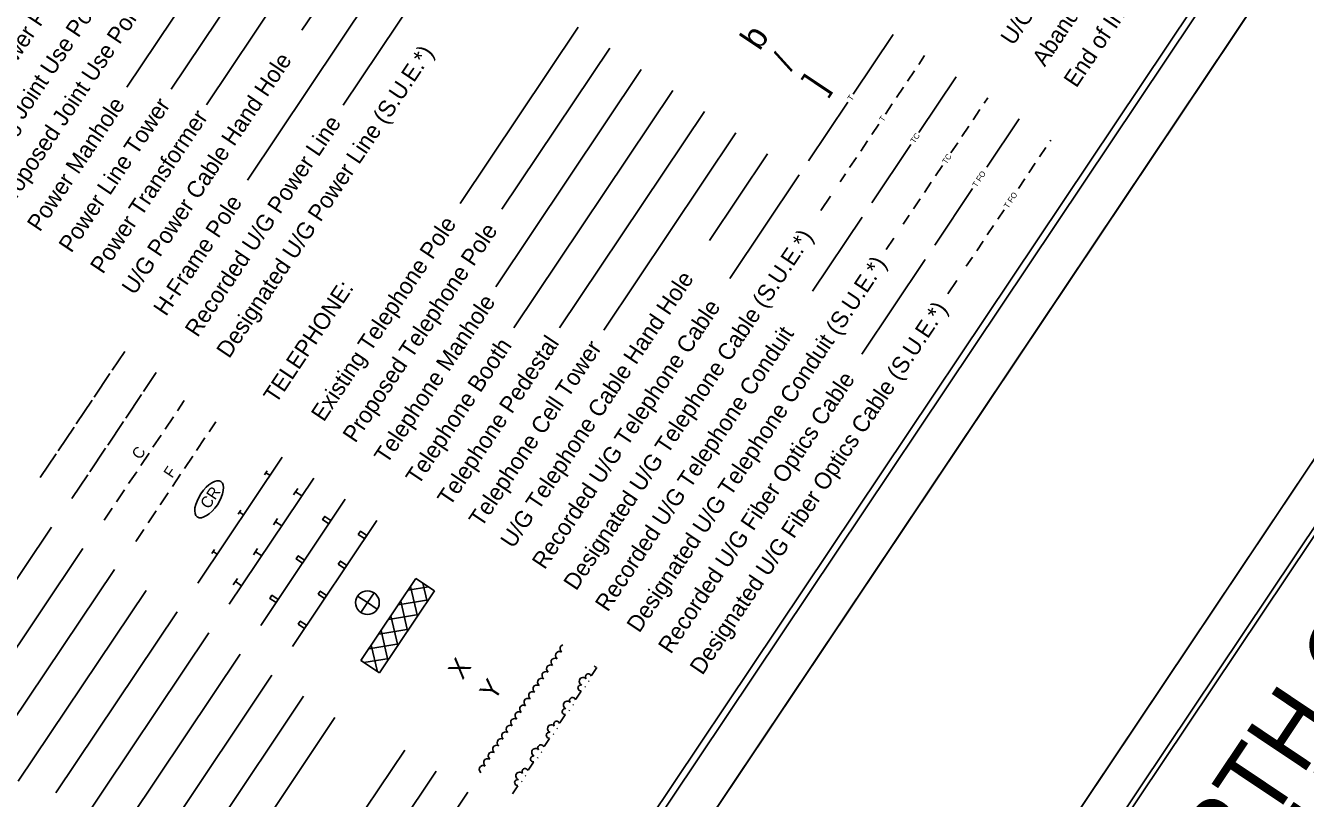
# Model space of a CAD drawing. Extents: x 1715610 to 1720914, y 798298 to 802505.
# Drawn here: x 1719036 to 1719710, y 799695 to 800102 of the extents above; entities that cross this region are included whole.
import ezdxf

# ---------------------------------------------------------------- set-up
doc = ezdxf.new("R2010")
doc.units = 0
for name, color, linetype in [('Prop WCC CELL', 7, 'Continuous'), ('Sheet Cutting Line CELL', 7, 'Continuous'), ('Sheet Plan CELL', 7, 'Continuous'), ('Sheet Plot Border Inside CELL', 7, 'Continuous'), ('Sheet Plot Border Outside CELL', 7, 'Continuous'), ('Sheet Symbology CELL', 7, 'Continuous'), ('Sheet Title CELL', 7, 'Continuous')]:
    doc.layers.add(name, color=color, linetype=linetype)

msp = doc.modelspace()

# ---------------------------------------------------------------- linework, layer by layer
at = {"layer": 'Prop WCC CELL'}
msp.add_ellipse((1719132.93, 799852.57), major_axis=(6.24, 9.32), ratio=0.462467, dxfattribs=at)
at = {"layer": 'Sheet Cutting Line CELL'}
for p, q in [((1718909.86, 798957.44), (1719846.53, 800356.9)), ((1720004.29, 800305.92), (1719067.89, 798906.88))]:
    msp.add_line(p, q, dxfattribs=at)
at = {"layer": 'Sheet Plan CELL'}
msp.add_lwpolyline([(1720013.54, 800279.28), (1719179.2, 799032.73), (1720051.79, 798448.69), (1720886.12, 799695.24)], close=True, dxfattribs=at)
at = {"layer": 'Sheet Plot Border Inside CELL'}
for points in [[(1718898.43, 798980.73), (1719825.37, 800365.65), (1718948.55, 800952.52), (1718021.61, 799567.6)], [(1719968.49, 798319.74), (1720895.15, 799704.24), (1720018.41, 800291.06), (1719091.75, 798906.55)]]:
    msp.add_lwpolyline(points, close=True, dxfattribs=at)
at = {"layer": 'Sheet Plot Border Outside CELL'}
for points in [[(1718909.86, 798957.44), (1719846.53, 800356.9), (1718932.4, 800968.75), (1717995.72, 799569.29)], [(1719977.88, 798297.81), (1720914.28, 799696.86), (1720004.29, 800305.92), (1719067.89, 798906.88)]]:
    msp.add_lwpolyline(points, close=True, dxfattribs=at)
at = {"layer": 'Sheet Symbology CELL'}
for p, q in [((1719177.74, 800201.43), (1719089.58, 800069.72)), ((1719194.36, 800190.31), (1719112.87, 800068.56)), ((1719210.98, 800179.19), (1719131.49, 800060.43)), ((1719227.6, 800168.06), (1719181.81, 800099.65)), ((1719244.22, 800156.94), (1719153.05, 800020.73)), ((1719260.84, 800145.81), (1719203.57, 800060.25)), ((1719327.32, 800101.31), (1719265.09, 800008.33)), ((1719472.11, 800065.94), (1719493.18, 800097.42)), ((1719343.94, 800090.19), (1719287.17, 800005.37)), ((1719506.7, 800081.66), (1719509.8, 800086.29)), ((1719360.56, 800079.07), (1719283.88, 799964.5)), ((1719500.86, 800072.93), (1719504.47, 800078.33)), ((1719506.72, 800045.74), (1719526.42, 800075.17)), ((1719377.18, 800067.94), (1719293.47, 799942.87)), ((1719495.02, 800064.21), (1719498.63, 800069.61)), ((1719448.68, 800030.93), (1719469.33, 800061.79)), ((1719489.18, 800055.48), (1719492.79, 800060.88)), ((1719535.3, 800052.48), (1719538.92, 800057.88)), ((1719541.14, 800061.21), (1719543.04, 800064.04)), ((1719393.81, 800056.82), (1719317.51, 799942.83)), ((1719542.63, 800027.47), (1719559.66, 800052.92)), ((1719410.43, 800045.69), (1719340.77, 799941.63)), ((1719482, 800044.76), (1719485.62, 800050.16)), ((1719529.46, 800043.76), (1719533.08, 800049.16)), ((1719476.16, 800036.03), (1719479.78, 800041.44)), ((1719481.92, 800008.68), (1719502.55, 800039.51)), ((1719523.62, 800035.03), (1719527.24, 800040.43)), ((1719570.35, 800032.93), (1719573.69, 800037.92)), ((1719575.91, 800041.24), (1719576.28, 800041.79)), ((1719427.05, 800034.57), (1719396.43, 799988.83)), ((1719470.32, 800027.31), (1719473.94, 800032.71)), ((1719515.56, 800022.98), (1719519.17, 800028.38)), ((1719564.79, 800024.62), (1719568.13, 800029.61)), ((1719443.67, 800023.44), (1719407.2, 799968.96)), ((1719465.3, 800019.81), (1719468.1, 800023.98)), ((1719509.72, 800014.25), (1719513.33, 800019.66)), ((1719559.23, 800016.31), (1719562.56, 800021.3)), ((1719460.29, 800012.32), (1719455.21, 800004.73)), ((1719503.88, 800005.53), (1719507.49, 800010.93)), ((1719515.16, 799986.44), (1719535.12, 800016.25)), ((1719548.38, 800000.11), (1719551.72, 800005.09)), ((1719476.91, 800001.19), (1719450.81, 799962.2)), ((1719498.54, 799997.56), (1719501.65, 800002.2)), ((1719542.82, 799991.8), (1719546.16, 799996.78)), ((1719493.53, 799990.07), (1719489.6, 799984.2)), ((1719537.26, 799983.49), (1719540.59, 799988.47)), ((1719510.15, 799978.95), (1719476.76, 799929.06)), ((1719531.78, 799975.31), (1719535.03, 799980.16)), ((1719526.77, 799967.82), (1719522.01, 799960.71)), ((1719081.8, 799920.53), (1719088.48, 799930.5)), ((1719072.35, 799906.4), (1719080.69, 799918.87)), ((1719098.42, 799909.41), (1719105.1, 799919.38)), ((1719062.89, 799892.28), (1719071.23, 799904.74)), ((1719088.97, 799895.28), (1719097.31, 799907.74)), ((1719119.8, 799904.54), (1719116.24, 799899.22)), ((1719053.43, 799878.15), (1719061.78, 799890.61)), ((1719079.51, 799881.15), (1719087.85, 799893.62)), ((1719114.07, 799895.98), (1719109.71, 799889.46)), ((1719136.42, 799893.42), (1719132.86, 799888.1)), ((1719107.65, 799886.38), (1719103.34, 799879.94)), ((1719130.7, 799884.86), (1719126.33, 799878.33)), ((1719043.98, 799864.02), (1719052.32, 799876.49)), ((1719070.05, 799867.02), (1719078.4, 799879.49)), ((1719101.28, 799876.87), (1719096.94, 799870.39)), ((1719124.27, 799875.26), (1719119.96, 799868.82)), ((1719126.89, 799808.34), (1719171.39, 799874.82)), ((1719060.6, 799852.9), (1719068.94, 799865.36)), ((1719094.75, 799867.1), (1719090.52, 799860.79)), ((1719117.9, 799865.74), (1719113.56, 799859.26)), ((1719188.01, 799863.69), (1719143.52, 799797.21)), ((1719162.16, 799865.52), (1719163.55, 799867.6)), ((1719164.93, 799865.17), (1719162.86, 799866.56)), ((1719088.35, 799857.55), (1719084.15, 799851.27)), ((1719111.37, 799855.98), (1719107.14, 799849.66)), ((1719177.35, 799854.86), (1719179.57, 799858.18)), ((1719181.74, 799854.32), (1719178.46, 799856.52)), ((1719160.14, 799786.09), (1719204.63, 799852.57)), ((1719077.61, 799841.51), (1719081.84, 799847.82)), ((1719104.97, 799846.42), (1719100.77, 799840.15)), ((1719148.26, 799844.74), (1719149.65, 799846.82)), ((1719151.03, 799844.39), (1719148.95, 799845.78)), ((1719166.78, 799839.07), (1719169, 799842.39)), ((1719049.81, 799837.82), (1718956.84, 799698.91)), ((1719094.23, 799830.38), (1719098.46, 799836.7)), ((1719171.17, 799838.53), (1719167.89, 799840.73)), ((1719176.76, 799774.96), (1719221.25, 799841.44)), ((1719066.43, 799826.69), (1719014.6, 799749.25)), ((1719134.35, 799823.97), (1719135.74, 799826.05)), ((1719137.12, 799823.62), (1719135.04, 799825.01)), ((1719156.21, 799823.28), (1719158.44, 799826.6)), ((1719160.61, 799822.74), (1719157.32, 799824.94)), ((1719083.06, 799815.57), (1719028.69, 799734.35)), ((1719145.64, 799807.49), (1719147.87, 799810.81)), ((1719150.04, 799806.95), (1719146.75, 799809.15)), ((1719212.89, 799767.57), (1719241.86, 799810.86)), ((1719241.86, 799810.86), (1719251.59, 799804.36)), ((1719099.68, 799804.44), (1719032.41, 799703.95)), ((1719216.32, 799798.09), (1719219.79, 799803.28)), ((1719251.59, 799804.36), (1719222.61, 799761.06)), ((1719248.47, 799806.44), (1719237.72, 799804.67)), ((1719242.63, 799790.98), (1719239, 799806.58)), ((1719247.78, 799798.66), (1719245.52, 799808.42)), ((1719211.12, 799801.57), (1719216.32, 799798.09)), ((1719212.84, 799792.9), (1719216.32, 799798.09)), ((1719216.32, 799798.09), (1719221.51, 799794.61)), ((1719248.42, 799799.62), (1719232.55, 799796.94)), ((1719237.46, 799783.25), (1719233.86, 799798.9)), ((1719116.11, 799793.26), (1719052.24, 799697.82)), ((1719243.24, 799791.89), (1719227.4, 799789.26)), ((1719232.29, 799775.52), (1719228.71, 799791.21)), ((1719132.73, 799782.13), (1719056.95, 799668.91)), ((1719238.07, 799784.16), (1719222.26, 799781.57)), ((1719227.14, 799767.83), (1719223.54, 799783.48)), ((1719232.93, 799776.47), (1719217.09, 799773.84)), ((1719221.65, 799761.7), (1719218.36, 799775.75)), ((1719317.85, 799774.62), (1719318.38, 799775.41)), ((1719318.38, 799775.41), (1719319.24, 799775.8)), ((1719319.24, 799775.8), (1719319.31, 799775.81)), ((1719149.35, 799771.01), (1719091.34, 799684.33)), ((1719213.38, 799767.23), (1719213.19, 799768.02)), ((1719227.75, 799768.75), (1719214.38, 799766.57)), ((1719313.13, 799767.56), (1719313.65, 799768.35)), ((1719313.65, 799768.35), (1719314.51, 799768.74)), ((1719314.51, 799768.74), (1719315.36, 799768.83)), ((1719315.36, 799768.83), (1719316.18, 799768.53)), ((1719315.42, 799770.18), (1719315.49, 799771.09)), ((1719315.63, 799769.32), (1719315.42, 799770.18)), ((1719315.49, 799771.09), (1719316.02, 799771.88)), ((1719316.25, 799768.54), (1719315.63, 799769.32)), ((1719316.02, 799771.88), (1719316.88, 799772.27)), ((1719316.88, 799772.27), (1719317.72, 799772.36)), ((1719317.72, 799772.36), (1719318.54, 799772.06)), ((1719317.78, 799773.71), (1719317.85, 799774.62)), ((1719317.99, 799772.85), (1719317.78, 799773.71)), ((1719318.61, 799772.07), (1719317.99, 799772.85)), ((1719222.61, 799761.06), (1719212.89, 799767.57)), ((1719308.4, 799760.5), (1719308.93, 799761.29)), ((1719308.93, 799761.29), (1719309.79, 799761.67)), ((1719309.79, 799761.67), (1719310.63, 799761.77)), ((1719310.63, 799761.77), (1719311.45, 799761.46)), ((1719310.69, 799763.11), (1719310.76, 799764.03)), ((1719310.9, 799762.25), (1719310.69, 799763.11)), ((1719310.76, 799764.03), (1719311.29, 799764.82)), ((1719311.52, 799761.48), (1719310.9, 799762.25)), ((1719311.29, 799764.82), (1719312.15, 799765.2)), ((1719312.15, 799765.2), (1719313, 799765.3)), ((1719313, 799765.3), (1719313.81, 799764.99)), ((1719313.05, 799766.64), (1719313.13, 799767.56)), ((1719313.26, 799765.78), (1719313.05, 799766.64)), ((1719313.88, 799765.01), (1719313.26, 799765.78)), ((1719334.4, 799759.7), (1719337.18, 799763.85)), ((1719165.97, 799759.88), (1719107.96, 799673.21)), ((1719304.2, 799754.22), (1719305.06, 799754.61)), ((1719305.06, 799754.61), (1719305.9, 799754.7)), ((1719305.9, 799754.7), (1719306.72, 799754.4)), ((1719305.96, 799756.05), (1719306.03, 799756.96)), ((1719306.17, 799755.19), (1719305.96, 799756.05)), ((1719306.03, 799756.96), (1719306.56, 799757.75)), ((1719306.79, 799754.41), (1719306.17, 799755.19)), ((1719306.56, 799757.75), (1719307.42, 799758.14)), ((1719307.42, 799758.14), (1719308.27, 799758.24)), ((1719308.27, 799758.24), (1719309.09, 799757.93)), ((1719308.33, 799759.58), (1719308.4, 799760.5)), ((1719308.53, 799758.72), (1719308.33, 799759.58)), ((1719309.16, 799757.94), (1719308.53, 799758.72)), ((1719332.84, 799756.47), (1719333.12, 799756.89)), ((1719182.59, 799748.76), (1719103.26, 799630.23)), ((1719301.24, 799748.99), (1719301.31, 799749.9)), ((1719301.44, 799748.13), (1719301.24, 799748.99)), ((1719301.31, 799749.9), (1719301.83, 799750.69)), ((1719302.06, 799747.35), (1719301.44, 799748.13)), ((1719301.83, 799750.69), (1719302.69, 799751.08)), ((1719302.69, 799751.08), (1719303.54, 799751.17)), ((1719303.54, 799751.17), (1719304.36, 799750.87)), ((1719303.6, 799752.52), (1719303.67, 799753.43)), ((1719303.81, 799751.66), (1719303.6, 799752.52)), ((1719303.67, 799753.43), (1719304.2, 799754.22)), ((1719304.43, 799750.88), (1719303.81, 799751.66)), ((1719326.05, 799747.23), (1719328.84, 799751.39)), ((1719330.89, 799753.56), (1719331.17, 799753.98)), ((1719296.51, 799741.92), (1719296.58, 799742.84)), ((1719296.71, 799741.06), (1719296.51, 799741.92)), ((1719296.58, 799742.84), (1719297.11, 799743.63)), ((1719297.34, 799740.28), (1719296.71, 799741.06)), ((1719297.11, 799743.63), (1719297.97, 799744.01)), ((1719297.97, 799744.01), (1719298.81, 799744.11)), ((1719298.81, 799744.11), (1719299.63, 799743.8)), ((1719298.87, 799745.45), (1719298.94, 799746.37)), ((1719299.08, 799744.59), (1719298.87, 799745.45)), ((1719298.94, 799746.37), (1719299.47, 799747.16)), ((1719299.7, 799743.82), (1719299.08, 799744.59)), ((1719299.47, 799747.16), (1719300.33, 799747.54)), ((1719300.33, 799747.54), (1719301.18, 799747.64)), ((1719301.18, 799747.64), (1719301.99, 799747.33)), ((1719322.55, 799741.1), (1719322.83, 799741.51)), ((1719324.5, 799744.01), (1719324.77, 799744.42)), ((1719199.21, 799737.63), (1719119.88, 799619.11)), ((1719291.78, 799734.86), (1719291.85, 799735.77)), ((1719291.99, 799734), (1719291.78, 799734.86)), ((1719291.85, 799735.77), (1719292.38, 799736.56)), ((1719292.38, 799736.56), (1719293.24, 799736.95)), ((1719293.24, 799736.95), (1719294.09, 799737.04)), ((1719294.09, 799737.04), (1719294.9, 799736.74)), ((1719294.14, 799738.39), (1719294.21, 799739.3)), ((1719294.35, 799737.53), (1719294.14, 799738.39)), ((1719294.21, 799739.3), (1719294.74, 799740.09)), ((1719294.97, 799736.75), (1719294.35, 799737.53)), ((1719294.74, 799740.09), (1719295.6, 799740.48)), ((1719295.6, 799740.48), (1719296.45, 799740.58)), ((1719296.45, 799740.58), (1719297.27, 799740.27)), ((1719317.71, 799734.77), (1719320.49, 799738.92)), ((1719287.05, 799727.79), (1719287.12, 799728.71)), ((1719287.26, 799726.93), (1719287.05, 799727.79)), ((1719287.12, 799728.71), (1719287.65, 799729.5)), ((1719287.65, 799729.5), (1719288.51, 799729.89)), ((1719288.51, 799729.89), (1719289.36, 799729.98)), ((1719289.36, 799729.98), (1719290.17, 799729.67)), ((1719289.42, 799731.33), (1719289.49, 799732.24)), ((1719289.62, 799730.47), (1719289.42, 799731.33)), ((1719289.49, 799732.24), (1719290.01, 799733.03)), ((1719290.24, 799729.69), (1719289.62, 799730.47)), ((1719290.01, 799733.03), (1719290.88, 799733.42)), ((1719290.88, 799733.42), (1719291.72, 799733.51)), ((1719291.72, 799733.51), (1719292.54, 799733.21)), ((1719292.61, 799733.22), (1719291.99, 799734)), ((1719314.21, 799728.63), (1719314.48, 799729.05)), ((1719316.15, 799731.54), (1719316.43, 799731.96)), ((1719282.32, 799720.73), (1719282.39, 799721.65)), ((1719282.39, 799721.65), (1719282.92, 799722.43)), ((1719282.92, 799722.43), (1719283.78, 799722.82)), ((1719283.78, 799722.82), (1719284.63, 799722.92)), ((1719284.63, 799722.92), (1719285.45, 799722.61)), ((1719284.69, 799724.26), (1719284.76, 799725.18)), ((1719284.89, 799723.4), (1719284.69, 799724.26)), ((1719284.76, 799725.18), (1719285.29, 799725.97)), ((1719285.52, 799722.62), (1719284.89, 799723.4)), ((1719285.29, 799725.97), (1719286.15, 799726.35)), ((1719286.15, 799726.35), (1719286.99, 799726.45)), ((1719286.99, 799726.45), (1719287.81, 799726.14)), ((1719287.88, 799726.16), (1719287.26, 799726.93)), ((1719309.37, 799722.3), (1719312.15, 799726.46)), ((1719235.93, 799720.45), (1719135.18, 799569.93)), ((1719277.6, 799713.67), (1719277.67, 799714.58)), ((1719277.67, 799714.58), (1719278.19, 799715.37)), ((1719278.19, 799715.37), (1719279.06, 799715.76)), ((1719279.06, 799715.76), (1719279.9, 799715.85)), ((1719279.9, 799715.85), (1719280.72, 799715.55)), ((1719279.96, 799717.2), (1719280.03, 799718.11)), ((1719280.17, 799716.34), (1719279.96, 799717.2)), ((1719280.03, 799718.11), (1719280.56, 799718.9)), ((1719280.79, 799715.56), (1719280.17, 799716.34)), ((1719280.56, 799718.9), (1719281.42, 799719.29)), ((1719281.42, 799719.29), (1719282.27, 799719.39)), ((1719282.27, 799719.39), (1719283.08, 799719.08)), ((1719282.53, 799719.87), (1719282.32, 799720.73)), ((1719283.15, 799719.09), (1719282.53, 799719.87)), ((1719305.86, 799716.17), (1719306.14, 799716.58)), ((1719307.81, 799719.08), (1719308.09, 799719.49)), ((1719252.55, 799709.32), (1719151.8, 799558.8)), ((1719275.23, 799710.13), (1719275.3, 799711.05)), ((1719275.44, 799709.27), (1719275.23, 799710.13)), ((1719275.3, 799711.05), (1719275.83, 799711.84)), ((1719276.06, 799708.5), (1719275.44, 799709.27)), ((1719275.83, 799711.84), (1719276.69, 799712.23)), ((1719276.69, 799712.23), (1719277.54, 799712.32)), ((1719277.54, 799712.32), (1719278.36, 799712.01)), ((1719277.8, 799712.81), (1719277.6, 799713.67)), ((1719278.42, 799712.03), (1719277.8, 799712.81)), ((1719301.02, 799709.84), (1719303.81, 799713.99)), ((1719292.68, 799697.37), (1719295.46, 799701.53)), ((1719297.52, 799703.7), (1719297.8, 799704.12)), ((1719299.47, 799706.61), (1719299.74, 799707.03)), ((1719269.17, 799698.2), (1719150.87, 799521.45))]:
    msp.add_line(p, q, dxfattribs=at)
for points in [[(1718943.72, 800940.72), (1718109.38, 799694.16), (1718981.12, 799110.7), (1719815.46, 800357.25)], [(1719196, 799839.67), (1719197.11, 799841.33), (1719193.79, 799843.55), (1719192.67, 799841.89)], [(1719211.51, 799834.08), (1719212.63, 799835.74), (1719215.95, 799833.52), (1719214.84, 799831.86)], [(1719182.09, 799818.89), (1719183.21, 799820.55), (1719179.88, 799822.78), (1719178.77, 799821.12)], [(1719200.94, 799818.29), (1719202.06, 799819.95), (1719205.38, 799817.73), (1719204.27, 799816.07)], [(1719168.19, 799798.12), (1719169.3, 799799.78), (1719165.98, 799802), (1719164.86, 799800.34)], [(1719190.38, 799802.5), (1719191.49, 799804.16), (1719194.81, 799801.94), (1719193.7, 799800.28)], [(1719179.81, 799786.71), (1719180.92, 799788.37), (1719184.25, 799786.15), (1719183.13, 799784.49)]]:
    msp.add_lwpolyline(points, close=True, dxfattribs=at)
for centre, radius, start, end in [((1719216.32, 799798.09), 6.25, 56.19944, 146.20398), ((1719216.32, 799798.09), 6.25, 326.19944, 56.20398), ((1719216.32, 799798.09), 6.25, 146.19944, 236.20398), ((1719216.32, 799798.09), 6.25, 236.19944, 326.20398), ((1719337.14, 799765.62), 1.58, 212.45607, 259.95404), ((1719328.8, 799753.16), 1.58, 74.64001, 275.43658), ((1719329.91, 799756.62), 2.06, 42.16881, 250.2413), ((1719332.69, 799758.97), 1.58, 16.97354, 217.77011), ((1719324.35, 799746.51), 1.58, 16.97354, 217.77011), ((1719320.45, 799740.69), 1.58, 74.64001, 275.43658), ((1719321.57, 799744.16), 2.06, 42.16881, 250.2413), ((1719316, 799734.04), 1.58, 16.97354, 217.77011), ((1719312.11, 799728.23), 1.58, 74.64001, 275.43658), ((1719313.23, 799731.69), 2.06, 42.16881, 250.2413), ((1719304.88, 799719.23), 2.06, 42.16881, 250.2413), ((1719307.66, 799721.58), 1.58, 16.97354, 217.77011), ((1719303.77, 799715.76), 1.58, 74.64001, 275.43658), ((1719296.54, 799706.76), 2.06, 42.16881, 250.2413), ((1719299.32, 799709.11), 1.58, 16.97354, 217.77011), ((1719295.43, 799703.3), 1.58, 74.64001, 275.43658)]:
    msp.add_arc(centre, radius, start, end, dxfattribs=at)

# ---------------------------------------------------------------- texts
at = {"layer": 'Prop WCC CELL'}
msp.add_text('CR', height=6, rotation=56.20506, dxfattribs=at).set_placement((1719132.76, 799847.01))
at = {"layer": 'Sheet Symbology CELL'}
for s, height, p in [('Abandoned According to Utility Records', 8.75, (1719573.12, 800080.04)), ('U/G Test Hole (S.U.E.*)', 8.75, (1719556.5, 800091.16)), ('End of Information', 8.75, (1719589.75, 800068.91)), ('Proposed Power Pole', 8.75, (1718993.85, 800026.41)), ('Existing Joint Use Pole', 8.75, (1719010.46, 800015.29)), ('Proposed Joint Use Pole', 8.75, (1719027.1, 800004.17)), ('b', 13.2, (1719422.88, 800088.39)), ('U/G Power Cable Hand Hole', 8.75, (1719093.59, 799959.68)), ('Designated U/G Power Line (S.U.E.*)', 8.75, (1719143.44, 799926.32)), ('/', 12.5, (1719439.41, 800077.75)), (']', 13.5, (1719456.16, 800065.94)), ('T', 3, (1719471.44, 800062.24)), ('Power Manhole', 8.75, (1719043.72, 799993.04)), ('Power Line Tower', 8.75, (1719060.33, 799981.93)), ('Power Transformer', 8.75, (1719076.94, 799970.79)), ('Recorded U/G Power Line', 8.75, (1719126.83, 799937.43)), ('T', 3, (1719488.11, 800051.2)), ('TC', 3, (1719504.55, 800039.79)), ('TC', 3, (1719521.31, 800028.88)), ('T FO', 3, (1719537.2, 800016.66)), ('H-Frame Pole', 8.75, (1719110.21, 799948.56)), ('T FO', 3, (1719553.8, 800005.51)), ('Existing Telephone Pole', 8.75, (1719193.31, 799892.93)), ('Proposed Telephone Pole', 8.75, (1719209.93, 799881.81)), ('Designated U/G Telephone Cable (S.U.E.*)', 8.75, (1719326.28, 799803.95)), ('Designated U/G Telephone Conduit (S.U.E.*)', 8.75, (1719359.52, 799781.7)), ('U/G Telephone Cable Hand Hole', 8.75, (1719293.04, 799826.2)), ('TELEPHONE:', 8.75, (1719168.19, 799902.45)), ('Telephone Manhole', 8.75, (1719226.55, 799870.68)), ('Recorded U/G Telephone Cable', 8.75, (1719309.66, 799815.07)), ('Designated U/G Fiber Optics Cable (S.U.E.*)', 8.75, (1719392.77, 799759.45)), ('Recorded U/G Telephone Conduit', 8.75, (1719342.9, 799792.82)), ('Telephone Pedestal', 8.75, (1719259.79, 799848.44)), ('Telephone Booth', 8.75, (1719243.17, 799859.56)), ('Telephone Cell Tower', 8.75, (1719276.42, 799837.32)), ('Recorded U/G Fiber Optics Cable', 8.75, (1719376.14, 799770.58)), ('C', 5.93, (1719096.64, 799873.06)), ('F', 5.93, (1719113.41, 799863.28)), ('X', 10, (1719266.44, 799757.05)), ('Y', 10, (1719283.06, 799745.93))]:
    msp.add_text(s, height=height, rotation=56.20506, dxfattribs=at).set_placement(p)
at = {"layer": 'Sheet Title CELL'}
for s, p in [('STATE OF NORTH CAROLINA', (1719485.41, 799372.94)), ('DIVISION OF HIGHWAYS', (1719553.8, 799400.99))]:
    msp.add_text(s, height=37.4998, rotation=56.20506, dxfattribs=at).set_placement(p)

doc.saveas('drawing.dxf')
